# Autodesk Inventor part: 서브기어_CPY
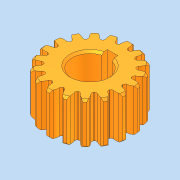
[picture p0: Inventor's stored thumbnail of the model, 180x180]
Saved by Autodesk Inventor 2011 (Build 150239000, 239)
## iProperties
Created: 2014-12
Part Number: 서브기어_CPY
Document SubType Name: Modeling
Designer: SDA
Mass: 15.166 g
Surface Area: 69.6172 cm^2
Volume: 15.166 cm^3
Density: 1 g/cm^3
Company: 한국ATC센터
Author: KYOUNG IL JANG
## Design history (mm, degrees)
sketch "스케치1"
  geometry: C1 r 15.5 at (0, 0); A1 r 1.155 centre (-2.906, 16.386) between (-2.542, 15.29) and (-1.751, 16.378); A2 r 5.602 centre (3.849, 16.522) between (-1.326, 18.666) and (-1.751, 16.378); A3 r 9.354 centre (7.378, 15.24) between (-0.682, 19.988) and (-1.326, 18.666); A4 r 1.155 centre (2.906, 16.386) between (1.751, 16.378) and (2.542, 15.29); A5 r 5.602 centre (-3.849, 16.522) between (1.751, 16.378) and (1.326, 18.666); A6 r 9.354 centre (-7.378, 15.24) between (1.326, 18.666) and (0.682, 19.988); A7 r 20 centre (0, 0) between (0.682, 19.988) and (-0.682, 19.988); A8 r 15.5 centre (0, 0) between (2.542, 15.29) and (-2.542, 15.29); 1 further point
  constraints: 16 point on circle, 9 centre point, 2 coincident
extrude "돌출1" new body sketch "스케치1" stored distance "d0" = 20; taper "d1" = 0 deg
extrude "돌출2" join sketch "스케치1" stored distance "d2" = 20; taper "d3" = 0 deg
chamfer "모따기1" distance "d4" = 1; stored, may be unused: second distance "d5" = 2, angle "d6" = 45 deg
hole "구멍1" diameter "d12" = 17; stored, may be unused: countersink angle "d16" = 90 deg, drill point angle "d18" = 118 deg; dims "d10" = 10, "d11" = 10, "d13" = 6, "d14" = 4, "d15" = 2, "d17" = 8
sketch "스케치2"
  geometry: L1 (-2.5, 8.124)-(-2.5, 10.8); L2 (-2.5, 10.8)-(2.5, 10.8); L3 (2.5, 10.8)-(2.5, 8.124); A1 r 8.5 centre (0, 0) between (-2.5, 8.124) and (2.5, 8.124) reference; 1 further point
  constraints: 6 end point, 2 parallel, 2 point on circle, 1 horizontal, 1 vertical
  dimensions: "d22" = 5 distance of L1.end L2.end; "d23" = 2.3 distance edge to line of A1 L2
extrude "돌출3" cut sketch "스케치2" stored distance "d24" = 20; taper "d25" = 0 deg
chamfer "모따기2" distance "d19" = 1; stored, may be unused: second distance "d20" = 2, angle "d21" = 45 deg
node "솔리드1"
pattern_circular "원형 패턴1" dims angle "d8" = 360 deg
